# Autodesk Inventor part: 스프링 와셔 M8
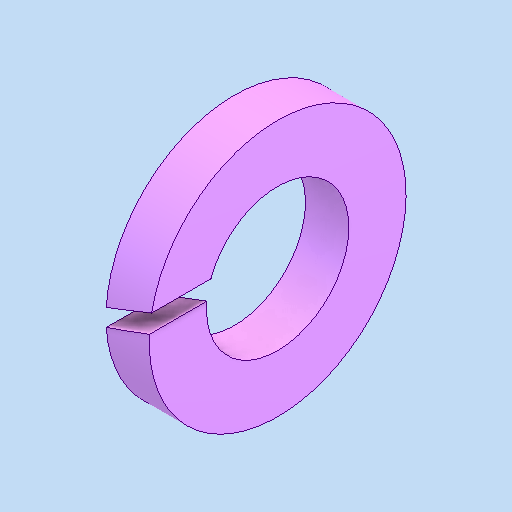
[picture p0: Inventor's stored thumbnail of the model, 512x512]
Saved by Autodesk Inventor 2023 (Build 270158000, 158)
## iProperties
Created: 2024-11
Part Number: 스프링 와셔 M8
Material: 강철, 연강
Description: 스프링 잠금 와셔
Document SubType Name: Modeling
Designer: asung
Density: 7.85 g/cm^3
Appearance: 기본값
Author: jhkim
Sending System: Autodesk Inventor 2025
Preprocessor: ST-DEVELOPER v20
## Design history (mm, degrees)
feature "Solid1"
node "솔리드1"
